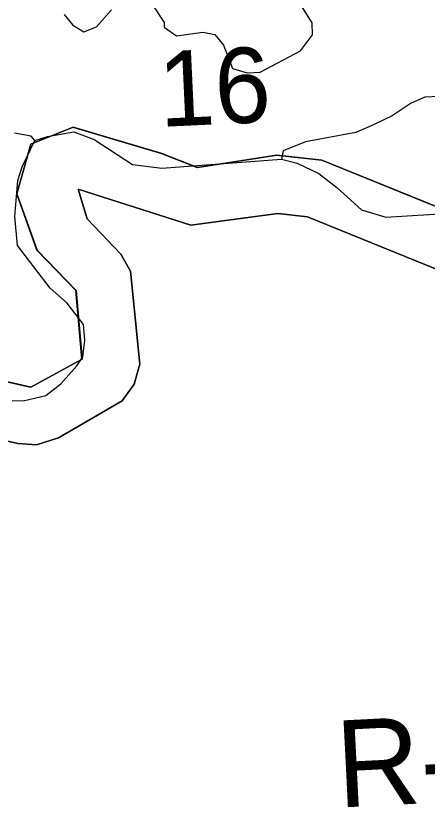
# Model space of a CAD drawing. Extents: x 128.7 to 185.5, y -21.4 to 12.6.
# Drawn here: x 160.65 to 161.361, y -16.381 to -15.015 of the extents above; entities that cross this region are included whole.
import ezdxf

# ---------------------------------------------------------------- set-up
doc = ezdxf.new("R2010")
doc.units = 0
for name, color, linetype in [('tdCoClipBndry', 7, 'Continuous'), ('tdCoCoBndry', 7, 'Continuous'), ('tdCoCoBndryPart', 7, 'Continuous'), ('tdCoHydroRiver', 7, 'Continuous'), ('tdCoSectNmbr', 7, 'Continuous'), ('tdCoTwpBndryShd', 7, 'Continuous'), ('tdCoTwpRngTxt', 7, 'Continuous')]:
    doc.layers.add(name, color=color, linetype=linetype)

msp = doc.modelspace()

# ---------------------------------------------------------------- linework, layer by layer
at = {"layer": 'tdCoClipBndry'}
msp.add_lwpolyline([(161.4332, -15.4757), (161.1536, -15.3626), (161.1027, -15.3568), (160.9527, -15.3768), (160.758, -15.3146), (160.7735, -15.3658), (160.8315, -15.4267), (160.848, -15.456), (160.8641, -15.6167), (160.8547, -15.651), (160.8339, -15.6798), (160.7237, -15.744), (160.6857, -15.7557), (160.6539, -15.7537), (160.5393, -15.7276)], dxfattribs=at)
at = {"layer": 'tdCoCoBndry'}
for p, q in [((160.749, -15.2074), (160.6764, -15.237)), ((160.6764, -15.237), (160.749, -15.2074)), ((160.9021, -15.2532), (160.749, -15.2074)), ((160.749, -15.2074), (160.9021, -15.2532)), ((160.6764, -15.237), (160.6522, -15.3229)), ((160.6522, -15.3229), (160.6764, -15.237)), ((160.9639, -15.2774), (160.9021, -15.2532)), ((160.9021, -15.2532), (160.9639, -15.2774)), ((161.101, -15.256), (160.9639, -15.2774)), ((160.9639, -15.2774), (161.101, -15.256)), ((161.1788, -15.2648), (161.101, -15.256)), ((161.101, -15.256), (161.1788, -15.2648)), ((161.5094, -15.3986), (161.1788, -15.2648)), ((161.1788, -15.2648), (161.5094, -15.3986)), ((160.6522, -15.3229), (160.6871, -15.4197)), ((160.6871, -15.4197), (160.6522, -15.3229)), ((160.6871, -15.4197), (160.7542, -15.4896)), ((160.7542, -15.4896), (160.6871, -15.4197)), ((160.7542, -15.4896), (160.7649, -15.6078)), ((160.7649, -15.6078), (160.7542, -15.4896)), ((160.7649, -15.6078), (160.6762, -15.6562)), ((160.6762, -15.6562), (160.7649, -15.6078)), ((160.6762, -15.6562), (160.5687, -15.6319)), ((160.5687, -15.6319), (160.6762, -15.6562))]:
    msp.add_line(p, q, dxfattribs=at)
for points in [[(160.5684, -15.6319), (160.6758, -15.6562), (160.7645, -15.6078), (160.7539, -15.4896), (160.6867, -15.4197), (160.6518, -15.3229), (160.676, -15.237), (160.7486, -15.2074), (160.9018, -15.2532), (160.9636, -15.2774), (161.1006, -15.256), (161.1785, -15.2648), (161.509, -15.3986)], [(161.5094, -15.3986), (161.1788, -15.2648), (161.101, -15.256), (160.9639, -15.2774), (160.9021, -15.2532), (160.749, -15.2074), (160.6764, -15.237), (160.6522, -15.3229), (160.6871, -15.4197), (160.7542, -15.4896), (160.7649, -15.6078), (160.6762, -15.6562), (160.5687, -15.6319)], [(161.5094, -15.3986), (161.1788, -15.2648), (161.101, -15.256), (160.9639, -15.2774), (160.9021, -15.2532), (160.749, -15.2074), (160.6764, -15.237), (160.6522, -15.3229), (160.6871, -15.4197), (160.7542, -15.4896), (160.7649, -15.6078), (160.6762, -15.6562), (160.5687, -15.6319)], [(160.5393, -15.7276), (160.6539, -15.7537), (160.6857, -15.7557), (160.7237, -15.744), (160.8339, -15.6798), (160.8547, -15.651), (160.8641, -15.6167), (160.848, -15.456), (160.8315, -15.4267), (160.7735, -15.3658), (160.758, -15.3146), (160.9527, -15.3768), (161.1027, -15.3568), (161.1536, -15.3626), (161.4332, -15.4757)]]:
    msp.add_lwpolyline(points, dxfattribs=at)
at = {"layer": 'tdCoCoBndryPart'}
msp.add_lwpolyline([(160.5684, -15.6319), (160.6758, -15.6562), (160.7645, -15.6078), (160.7539, -15.4896), (160.6867, -15.4197), (160.6518, -15.3229), (160.676, -15.237), (160.7486, -15.2074), (160.9018, -15.2532), (160.9636, -15.2774), (161.1006, -15.256), (161.1785, -15.2648), (161.509, -15.3986)], dxfattribs=at)
at = {"layer": 'tdCoHydroRiver'}
for points in [[(160.7337, -15.0129), (160.7485, -15.0313), (160.7679, -15.0432), (160.7897, -15.0345), (160.8155, -15.0052)], [(160.8862, -14.9964), (160.9062, -15.0272), (160.9065, -15.0351), (160.9276, -15.0501), (160.9731, -15.0438), (160.9938, -15.0478), (161.0087, -15.0662), (161.0243, -15.1066), (161.0498, -15.1136), (161.0719, -15.1128), (161.1416, -15.0756), (161.1627, -15.048), (161.162, -15.0275), (161.1453, -15.0013)], [(161.407, -15.1537), (161.3562, -15.1556), (161.3328, -15.166), (161.3001, -15.1878), (161.2689, -15.2032), (161.2376, -15.217), (161.1507, -15.233), (161.1116, -15.2487), (161.1088, -15.2631)], [(160.6439, -15.6791), (160.6628, -15.68), (160.702, -15.6707), (160.7281, -15.6508), (160.7554, -15.6198), (160.7659, -15.6037), (160.7696, -15.5751), (160.767, -15.5484), (160.7389, -15.5115), (160.7096, -15.4857), (160.6532, -15.412), (160.6483, -15.3616), (160.654, -15.2999), (160.661, -15.2759), (160.6831, -15.2309), (160.7049, -15.2238), (160.7504, -15.2159), (160.7856, -15.2288), (160.8519, -15.2722), (160.9026, -15.2783), (161.1088, -15.2631), (161.1361, -15.27), (161.1734, -15.2877), (161.2045, -15.3119), (161.2473, -15.35), (161.2891, -15.3628), (161.4, -15.3558)], [(160.6831, -15.2309), (160.6765, -15.2233), (160.6479, -15.218)]]:
    msp.add_lwpolyline(points, dxfattribs=at)
at = {"layer": 'tdCoTwpBndryShd'}
msp.add_lwpolyline([(160.5684, -15.6319), (160.6758, -15.6562), (160.7645, -15.6078), (160.7539, -15.4896), (160.6867, -15.4197), (160.6518, -15.3229), (160.676, -15.237), (160.7486, -15.2074), (160.9018, -15.2532), (160.9636, -15.2774), (161.1006, -15.256), (161.1785, -15.2648), (161.509, -15.3986)], dxfattribs=at)

# ---------------------------------------------------------------- texts
at = {"layer": 'tdCoSectNmbr'}
msp.add_text('16', height=0.13, rotation=2.6732, dxfattribs=at).set_placement((160.8996, -15.2072))
at = {"layer": 'tdCoTwpRngTxt'}
msp.add_text('R-5E', height=0.15, rotation=2.8681, dxfattribs=at).set_placement((161.2072, -16.382))

doc.saveas('drawing.dxf')
